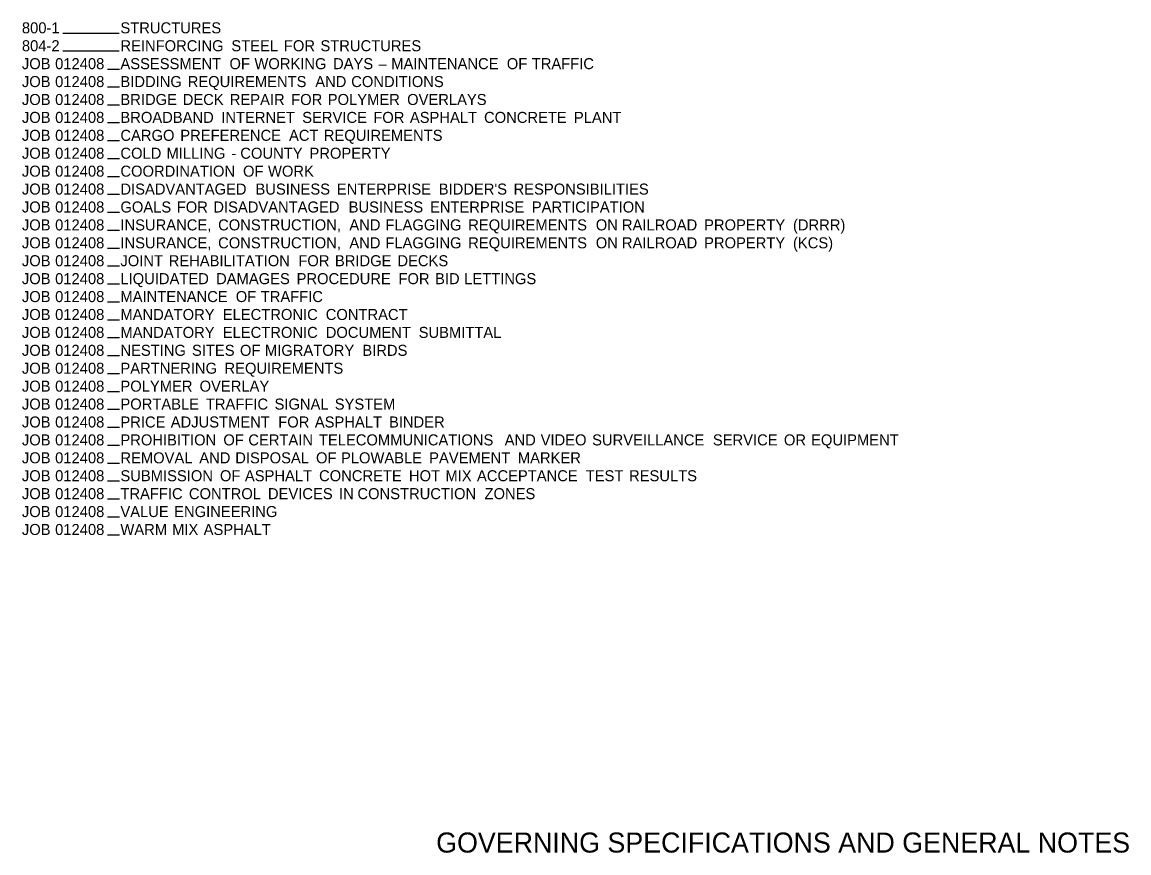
# Model space of a CAD drawing. Extents: x 1930579 to 1932218, y 596452 to 599494.
# Drawn here: x 1931525 to 1932188, y 598494 to 598992 of the extents above; entities that cross this region are included whole.
import ezdxf

# ---------------------------------------------------------------- set-up
doc = ezdxf.new("R2010")
doc.units = 0
doc.layers.add('Default', color=7, linetype='Continuous')
doc.layers.add('R_Border', color=7, linetype='Continuous')

msp = doc.modelspace()

# ---------------------------------------------------------------- linework, layer by layer
at = {"layer": 'R_Border'}
for p, q in [((1931549.9, 598985.04), (1931583.53, 598985.04)), ((1931549.9, 598974.32), (1931583.53, 598974.32)), ((1931576.59, 598963.44), (1931583.8, 598963.44)), ((1931576.59, 598952.87), (1931583.8, 598952.87)), ((1931576.59, 598942.14), (1931583.8, 598942.14)), ((1931576.59, 598931.42), (1931583.8, 598931.42)), ((1931576.59, 598920.69), (1931583.8, 598920.69)), ((1931576.59, 598909.97), (1931583.8, 598909.97)), ((1931576.59, 598899.24), (1931583.8, 598899.24)), ((1931576.59, 598888.52), (1931583.8, 598888.52)), ((1931576.59, 598877.79), (1931583.8, 598877.79)), ((1931576.59, 598867.07), (1931583.8, 598867.07)), ((1931576.59, 598856.34), (1931583.8, 598856.34)), ((1931576.59, 598845.62), (1931583.8, 598845.62)), ((1931576.59, 598834.89), (1931583.8, 598834.89)), ((1931576.59, 598824.17), (1931583.8, 598824.17)), ((1931576.59, 598813.44), (1931583.8, 598813.44)), ((1931576.59, 598802.72), (1931583.8, 598802.72)), ((1931576.59, 598791.99), (1931583.8, 598791.99)), ((1931576.59, 598781.27), (1931583.8, 598781.27)), ((1931576.59, 598770.54), (1931583.8, 598770.54)), ((1931576.59, 598759.82), (1931583.8, 598759.82)), ((1931576.59, 598749.09), (1931583.8, 598749.09)), ((1931576.59, 598738.37), (1931583.8, 598738.37)), ((1931576.59, 598727.64), (1931583.8, 598727.64)), ((1931576.59, 598716.92), (1931583.8, 598716.92)), ((1931576.59, 598706.19), (1931583.8, 598706.19)), ((1931576.59, 598695.47), (1931583.8, 598695.47)), ((1931576.59, 598684.74), (1931583.8, 598684.74))]:
    msp.add_line(p, q, dxfattribs=at)

# ---------------------------------------------------------------- texts
at = {"layer": 'Default'}
for s, p in [('800-1', (1931525.34, 598984.85)), ('STRUCTURES', (1931584.33, 598984.85)), ('804-2', (1931525.34, 598974.13)), ('REINFORCING', (1931584.33, 598974.13)), (' STEEL', (1931648.3, 598974.13)), (' FOR', (1931679.76, 598974.13)), (' STRUCTURES', (1931701.66, 598974.13)), ('JOB', (1931525.34, 598963.4)), (' 012408', (1931542.79, 598963.4)), ('ASSESSMENT', (1931584.33, 598963.4)), (' OF', (1931647.18, 598963.4)), (' WORKING', (1931662.13, 598963.4)), (' DAYS', (1931709.19, 598963.4)), ('–', (1931738.95, 598963.4)), (' MAINTENANCE', (1931744.05, 598963.4)), (' OF', (1931813.25, 598963.4)), (' TRAFFIC', (1931828.19, 598963.4)), ('JOB', (1931525.34, 598952.68)), (' 012408', (1931542.79, 598952.68)), ('BIDDING', (1931584.33, 598952.68)), (' REQUIREMENTS', (1931622.18, 598952.68)), (' AND', (1931698.55, 598952.68)), (' CONDITIONS', (1931720.09, 598952.68)), ('JOB', (1931525.34, 598941.95)), (' 012408', (1931542.79, 598941.95)), ('BRIDGE', (1931584.33, 598941.95)), (' DECK', (1931619.19, 598941.95)), (' REPAIR', (1931647.36, 598941.95)), (' FOR', (1931684.13, 598941.95)), (' POLYMER', (1931706.03, 598941.95)), (' OVERLAYS', (1931753.57, 598941.95)), ('JOB', (1931525.34, 598931.23)), (' 012408', (1931542.79, 598931.23)), ('BROADBAND', (1931584.33, 598931.23)), (' INTERNET', (1931642.26, 598931.23)), (' SERVICE', (1931690.75, 598931.23)), (' FOR', (1931733.3, 598931.23)), (' ASPHALT', (1931755.21, 598931.23)), (' CONCRETE', (1931799.61, 598931.23)), (' PLANT', (1931853.43, 598931.23)), ('JOB', (1931525.34, 598920.5)), (' 012408', (1931542.79, 598920.5)), ('CARGO', (1931584.33, 598920.5)), (' PREFERENCE', (1931617.73, 598920.5)), (' ACT', (1931682.84, 598920.5)), (' REQUIREMENTS', (1931703.66, 598920.5)), ('JOB', (1931525.34, 598909.78)), (' 012408', (1931542.79, 598909.78)), ('COLD', (1931584.33, 598909.78)), (' MILLING', (1931609.45, 598909.78)), (' -', (1931648.32, 598909.78)), (' COUNTY', (1931653.67, 598909.78)), (' PROPERTY', (1931695.1, 598909.78)), ('JOB', (1931525.34, 598899.05)), (' 012408', (1931542.79, 598899.05)), ('COORDINATION', (1931584.33, 598899.05)), (' OF', (1931655.3, 598899.05)), (' WORK', (1931670.25, 598899.05)), ('JOB', (1931525.34, 598888.33)), (' 012408', (1931542.79, 598888.33)), ('DISADVANTAGED', (1931584.33, 598888.33)), (' BUSINESS', (1931662.76, 598888.33)), (' ENTERPRISE', (1931711.48, 598888.33)), (" BIDDER'S", (1931772.48, 598888.33)), (' RESPONSIBILITIES', (1931817.32, 598888.33)), ('JOB', (1931525.34, 598877.6)), (' 012408', (1931542.79, 598877.6)), ('GOALS', (1931584.33, 598877.6)), (' FOR', (1931615.62, 598877.6)), (' DISADVANTAGED', (1931637.52, 598877.6)), (' BUSINESS', (1931718.52, 598877.6)), (' ENTERPRISE', (1931767.24, 598877.6)), (' PARTICIPATION', (1931828.24, 598877.6)), ('JOB', (1931525.34, 598866.88)), (' 012408', (1931542.79, 598866.88)), ('INSURANCE,', (1931584.33, 598866.88)), (' CONSTRUCTION,', (1931640.39, 598866.88)), (' AND', (1931718.98, 598866.88)), (' FLAGGING', (1931740.52, 598866.88)), (' REQUIREMENTS', (1931790.15, 598866.88)), (' ON', (1931866.53, 598866.88)), (' RAILROAD', (1931882.17, 598866.88)), (' PROPERTY', (1931931.39, 598866.88)), (' (DRRR)', (1931984.61, 598866.88)), ('JOB', (1931525.34, 598856.15)), (' 012408', (1931542.79, 598856.15)), ('INSURANCE,', (1931584.33, 598856.15)), (' CONSTRUCTION,', (1931640.39, 598856.15)), (' AND', (1931718.98, 598856.15)), (' FLAGGING', (1931740.52, 598856.15)), (' REQUIREMENTS', (1931790.15, 598856.15)), (' ON', (1931866.53, 598856.15)), (' RAILROAD', (1931882.17, 598856.15)), (' PROPERTY', (1931931.39, 598856.15)), (' (KCS)', (1931984.61, 598856.15)), ('JOB', (1931525.34, 598845.43)), (' 012408', (1931542.79, 598845.43)), ('JOINT', (1931584.33, 598845.43)), (' REHABILITATION', (1931610.78, 598845.43)), (' FOR', (1931688.43, 598845.43)), (' BRIDGE', (1931710.33, 598845.43)), (' DECKS', (1931747.76, 598845.43)), ('JOB', (1931525.34, 598834.7)), (' 012408', (1931542.79, 598834.7)), ('LIQUIDATED', (1931584.33, 598834.7)), (' DAMAGES', (1931639.17, 598834.7)), (' PROCEDURE', (1931687.38, 598834.7)), (' FOR', (1931748.38, 598834.7)), (' BID', (1931770.28, 598834.7)), (' LETTINGS', (1931787.72, 598834.7)), ('JOB', (1931525.34, 598823.98)), (' 012408', (1931542.79, 598823.98)), ('MAINTENANCE', (1931584.33, 598823.98)), (' OF', (1931650.96, 598823.98)), (' TRAFFIC', (1931665.91, 598823.98)), ('JOB', (1931525.34, 598813.25)), (' 012408', (1931542.79, 598813.25)), ('MANDATORY', (1931584.33, 598813.25)), (' ELECTRONIC', (1931643.18, 598813.25)), (' CONTRACT', (1931704.82, 598813.25)), ('JOB', (1931525.34, 598802.53)), (' 012408', (1931542.79, 598802.53)), ('MANDATORY', (1931584.33, 598802.53)), (' ELECTRONIC', (1931643.18, 598802.53)), (' DOCUMENT', (1931704.82, 598802.53)), (' SUBMITTAL', (1931760.47, 598802.53)), ('JOB', (1931525.34, 598791.8)), (' 012408', (1931542.79, 598791.8)), ('NESTING', (1931584.33, 598791.8)), (' SITES', (1931624.74, 598791.8)), (' OF', (1931653.47, 598791.8)), (' MIGRATORY', (1931668.42, 598791.8)), (' BIRDS', (1931726.76, 598791.8)), ('JOB', (1931525.34, 598781.08)), (' 012408', (1931542.79, 598781.08)), ('PARTNERING', (1931584.33, 598781.08)), (' REQUIREMENTS', (1931644.21, 598781.08)), ('JOB', (1931525.34, 598770.35)), (' 012408', (1931542.79, 598770.35)), ('POLYMER', (1931584.33, 598770.35)), (' OVERLAY', (1931629.3, 598770.35)), ('JOB', (1931525.34, 598759.63)), (' 012408', (1931542.79, 598759.63)), ('PORTABLE', (1931584.33, 598759.63)), (' TRAFFIC', (1931633.04, 598759.63)), (' SIGNAL', (1931674.17, 598759.63)), (' SYSTEM', (1931710.22, 598759.63)), ('JOB', (1931525.34, 598748.9)), (' 012408', (1931542.79, 598748.9)), ('PRICE', (1931584.33, 598748.9)), (' ADJUSTMENT', (1931612.02, 598748.9)), (' FOR', (1931676.39, 598748.9)), (' ASPHALT', (1931698.3, 598748.9)), (' BINDER', (1931742.7, 598748.9)), ('JOB', (1931525.34, 598738.18)), (' 012408', (1931542.79, 598738.18)), ('PROHIBITION', (1931584.33, 598738.18)), (' OF', (1931643.52, 598738.18)), (' CERTAIN', (1931658.47, 598738.18)), (' TELECOMMUNICATIONS', (1931700.75, 598738.18)), (' AND', (1931811.97, 598738.18)), (' VIDEO', (1931833.51, 598738.18)), (' SURVEILLANCE', (1931864.35, 598738.18)), (' SERVICE', (1931936.64, 598738.18)), (' OR', (1931979.19, 598738.18)), (' EQUIPMENT', (1931995.46, 598738.18)), ('JOB', (1931525.34, 598727.45)), (' 012408', (1931542.79, 598727.45)), ('REMOVAL', (1931584.33, 598727.45)), (' AND', (1931629.1, 598727.45)), (' DISPOSAL', (1931650.64, 598727.45)), (' OF', (1931699, 598727.45)), (' PLOWABLE', (1931713.95, 598727.45)), (' PAVEMENT', (1931766.75, 598727.45)), (' MARKER', (1931819.86, 598727.45)), ('JOB', (1931525.34, 598716.73)), (' 012408', (1931542.79, 598716.73)), ('SUBMISSION', (1931584.33, 598716.73)), (' OF', (1931641.48, 598716.73)), (' ASPHALT', (1931656.42, 598716.73)), (' CONCRETE', (1931700.83, 598716.73)), (' HOT', (1931754.65, 598716.73)), (' MIX', (1931776.49, 598716.73)), (' ACCEPTANCE', (1931795.39, 598716.73)), (' TEST', (1931860.49, 598716.73)), (' RESULTS', (1931886.44, 598716.73)), ('JOB', (1931525.34, 598706)), (' 012408', (1931542.79, 598706)), ('TRAFFIC', (1931584.33, 598706)), (' CONTROL', (1931622.9, 598706)), (' DEVICES', (1931670.22, 598706)), (' IN', (1931712.79, 598706)), (' CONSTRUCTION', (1931723.81, 598706)), (' ZONES', (1931799.91, 598706)), ('JOB', (1931525.34, 598695.28)), (' 012408', (1931542.79, 598695.28)), ('VALUE', (1931584.33, 598695.28)), (' ENGINEERING', (1931614.08, 598695.28)), ('JOB', (1931525.34, 598684.55)), (' 012408', (1931542.79, 598684.55)), ('WARM', (1931584.33, 598684.55)), (' MIX', (1931612.83, 598684.55)), (' ASPHALT', (1931631.72, 598684.55))]:
    msp.add_text(s, height=6.6, dxfattribs=at).set_placement(p)
at = {"layer": 'R_Border'}
msp.add_text('GOVERNING SPECIFICATIONS AND GENERAL NOTES ', height=12, rotation=360, dxfattribs=at).set_placement((1931773.43, 598494.45))

doc.saveas('drawing.dxf')
